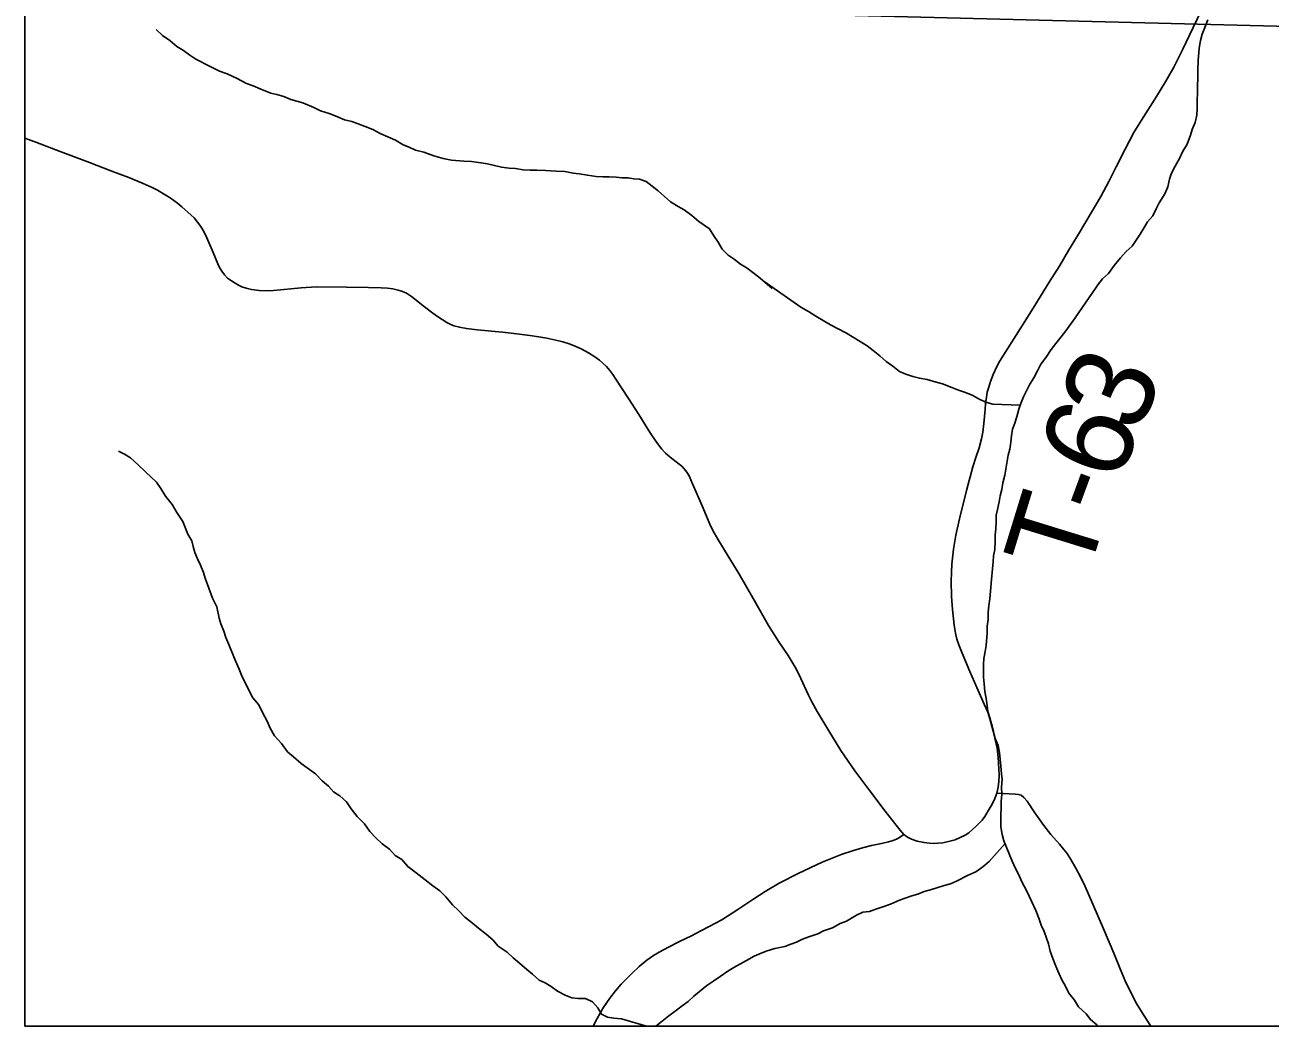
# Model space of a CAD drawing. Extents: x -3.3 to 34, y 0 to 56.8.
# Drawn here: x -3.304 to -2.5, y 28.077 to 28.724 of the extents above; entities that cross this region are included whole.
import ezdxf

# ---------------------------------------------------------------- set-up
doc = ezdxf.new("R2010")
doc.units = 0
for name, color, linetype in [('GM_X_Corporation', 7, 'Continuous'), ('GM_X_Township_Road', 7, 'Continuous'), ('GM_X_Township_Road_Text', 7, 'Continuous'), ('GT_Project_Soil_Layers', 7, 'Continuous'), ('SH_Data', 7, 'Continuous')]:
    doc.layers.add(name, color=color, linetype=linetype)

msp = doc.modelspace()

# ---------------------------------------------------------------- linework, layer by layer
at = {"layer": 'GM_X_Corporation'}
msp.add_lwpolyline([(-3.30393, 33.7379), (-3.30393, 28.07705), (1.56989, 28.07705), (1.59424, 28.73823), (1.64589, 29.81689), (1.65379, 30.0279), (1.68495, 30.79802), (1.68821, 30.98908), (1.68831, 30.9953), (1.68852, 31.00753), (1.69805, 31.56614), (1.74587, 32.36303)], dxfattribs=at)
msp.add_lwpolyline([(-3.30393, 29.75009), (-3.30393, 28.74342), (-2.4361, 28.72137), (-2.4143, 29.73246)], close=True, dxfattribs=at)
at = {"layer": 'GM_X_Township_Road'}
for points in [[(-2.67635, 28.22737), (-2.67545, 28.23132), (-2.67504, 28.23493), (-2.67479, 28.23913), (-2.67542, 28.25075), (-2.67624, 28.25659), (-2.67756, 28.26292), (-2.67871, 28.26744), (-2.68093, 28.2755), (-2.68225, 28.27969), (-2.68447, 28.28503), (-2.68931, 28.29563), (-2.69371, 28.30598), (-2.69877, 28.31791), (-2.70095, 28.32335), (-2.70214, 28.32687), (-2.70313, 28.33074), (-2.70395, 28.33592), (-2.70509, 28.34619), (-2.70559, 28.35458), (-2.70583, 28.36428), (-2.70573, 28.37007), (-2.70541, 28.37526), (-2.70428, 28.38514), (-2.70278, 28.39418), (-2.70055, 28.40469), (-2.69602, 28.42283), (-2.69177, 28.43816), (-2.68999, 28.44425), (-2.68785, 28.45049), (-2.68631, 28.45635), (-2.68547, 28.46063), (-2.68474, 28.46619), (-2.68397, 28.47517), (-2.68364, 28.47919), (-2.68314, 28.48331), (-2.68257, 28.48643), (-2.68178, 28.48911), (-2.68046, 28.49337), (-2.6787, 28.49794), (-2.67644, 28.50292), (-2.67461, 28.50632), (-2.67106, 28.51208), (-2.66388, 28.52332), (-2.65722, 28.53374), (-2.65009, 28.54525), (-2.64257, 28.55737), (-2.6358, 28.5683), (-2.63004, 28.57792), (-2.6237, 28.5885), (-2.61553, 28.60214), (-2.60921, 28.61269), (-2.60399, 28.62244), (-2.59926, 28.63186), (-2.59355, 28.64327), (-2.58787, 28.65403), (-2.58516, 28.65864), (-2.58303, 28.66201), (-2.57323, 28.67726), (-2.56724, 28.68717), (-2.56207, 28.69637), (-2.55648, 28.70755), (-2.5497, 28.72183), (-2.54447, 28.73271)], [(-3.30393, 28.65038), (-3.29681, 28.64792), (-3.28111, 28.64192), (-3.26225, 28.63473), (-3.24839, 28.62944), (-3.23682, 28.62502), (-3.22756, 28.62118), (-3.22185, 28.61857), (-3.21835, 28.61678), (-3.2134, 28.61391), (-3.21018, 28.61183), (-3.20548, 28.60843), (-3.20253, 28.60608), (-3.19475, 28.59901), (-3.19093, 28.59425), (-3.18966, 28.59234), (-3.18792, 28.58937), (-3.18643, 28.58619), (-3.18581, 28.58458), (-3.1824, 28.57654), (-3.17935, 28.56934), (-3.17828, 28.56703), (-3.1768, 28.56465), (-3.17499, 28.5621), (-3.17302, 28.56005), (-3.17063, 28.55832), (-3.16825, 28.55676), (-3.16603, 28.55552), (-3.1639, 28.55445), (-3.16116, 28.55353), (-3.15756, 28.55265), (-3.15271, 28.55199), (-3.14704, 28.55183), (-3.14351, 28.55207), (-3.12565, 28.55384), (-3.11556, 28.55445), (-3.09632, 28.55432), (-3.08202, 28.55412), (-3.07388, 28.55388), (-3.06977, 28.55355), (-3.06632, 28.55306), (-3.06303, 28.5524), (-3.06015, 28.5515), (-3.05744, 28.55026), (-3.05424, 28.54813), (-3.04585, 28.54163), (-3.04051, 28.53744), (-3.03755, 28.53522), (-3.03451, 28.53325), (-3.03146, 28.53136), (-3.02928, 28.53024), (-3.02696, 28.52934), (-3.02333, 28.52831), (-3.01889, 28.52749), (-3.0119, 28.52667), (-2.99562, 28.52511), (-2.98634, 28.52412), (-2.97787, 28.52306), (-2.9722, 28.52215), (-2.96685, 28.52125), (-2.9611, 28.52001), (-2.9565, 28.51886), (-2.95247, 28.51754), (-2.94869, 28.51615), (-2.94425, 28.51418), (-2.94005, 28.51187), (-2.93595, 28.50932), (-2.93282, 28.50711), (-2.92846, 28.503), (-2.92617, 28.50045), (-2.92436, 28.4979), (-2.92238, 28.49475), (-2.91415, 28.48225), (-2.90756, 28.47194), (-2.90019, 28.46009), (-2.89707, 28.45548), (-2.89476, 28.45236), (-2.89262, 28.44965), (-2.89024, 28.4471), (-2.88737, 28.44447), (-2.88145, 28.43987), (-2.87981, 28.43863), (-2.87824, 28.4369), (-2.87651, 28.43468), (-2.87511, 28.4323), (-2.87282, 28.42729), (-2.86665, 28.41299), (-2.86164, 28.40123), (-2.85966, 28.3972), (-2.85654, 28.39153), (-2.8498, 28.38043), (-2.84306, 28.36934), (-2.83313, 28.35203), (-2.82382, 28.3358), (-2.81719, 28.32519), (-2.81116, 28.31628), (-2.80658, 28.30892), (-2.80422, 28.30436), (-2.79798, 28.29077), (-2.79578, 28.28641), (-2.79248, 28.28018), (-2.78486, 28.26782), (-2.77705, 28.25499), (-2.76809, 28.24184), (-2.75838, 28.22892), (-2.7484, 28.21589), (-2.74146, 28.20682), (-2.73882, 28.20354), (-2.73634, 28.2007)], [(-2.73634, 28.2007), (-2.73412, 28.19907), (-2.73142, 28.19776), (-2.72792, 28.19656), (-2.72334, 28.19556), (-2.71986, 28.19516), (-2.71735, 28.19506), (-2.7145, 28.19513), (-2.7113, 28.19544), (-2.70669, 28.19638), (-2.70332, 28.19744), (-2.70005, 28.19879), (-2.69691, 28.20046), (-2.69456, 28.20196), (-2.68942, 28.20633), (-2.68588, 28.21008), (-2.68409, 28.21251), (-2.68122, 28.21712), (-2.67936, 28.22042), (-2.67776, 28.22397), (-2.67635, 28.22737)], [(-2.67635, 28.22737), (-2.66435, 28.22688), (-2.66246, 28.22663), (-2.66074, 28.22614), (-2.65885, 28.22474), (-2.65687, 28.22236), (-2.65178, 28.21471), (-2.64594, 28.20649), (-2.64142, 28.2008), (-2.63582, 28.19449), (-2.63303, 28.1912), (-2.63098, 28.18849), (-2.62851, 28.18455), (-2.62539, 28.17895), (-2.62218, 28.17304), (-2.6193, 28.16712), (-2.61437, 28.15586), (-2.60759, 28.13989), (-2.60089, 28.12412), (-2.5967, 28.11393), (-2.59341, 28.10629), (-2.59028, 28.09971), (-2.5861, 28.09158), (-2.58127, 28.08363), (-2.57697, 28.07705)], [(-2.93699, 28.07705), (-2.93442, 28.08186), (-2.9305, 28.08877), (-2.92615, 28.09519), (-2.92256, 28.09992), (-2.9189, 28.10419), (-2.91233, 28.11085), (-2.90731, 28.11553), (-2.9023, 28.11964), (-2.8981, 28.1226), (-2.89449, 28.12482), (-2.88832, 28.12811), (-2.88118, 28.13169), (-2.87353, 28.1354), (-2.86745, 28.13847), (-2.86202, 28.14134), (-2.85388, 28.14578), (-2.8436, 28.15228), (-2.83382, 28.15885), (-2.82591, 28.16398), (-2.81687, 28.16925), (-2.80462, 28.17567), (-2.78905, 28.18297), (-2.78169, 28.18599), (-2.77624, 28.18801), (-2.76951, 28.19026), (-2.76307, 28.19215), (-2.75722, 28.19362), (-2.7508, 28.19502), (-2.74638, 28.19608), (-2.74339, 28.19687), (-2.74082, 28.19791), (-2.73852, 28.19917), (-2.73634, 28.2007)]]:
    msp.add_lwpolyline(points, dxfattribs=at)
at = {"layer": 'GT_Project_Soil_Layers'}
for points in [[(-3.21923, 28.72055), (-3.21501, 28.71682), (-3.21041, 28.71346), (-3.20581, 28.70973), (-3.20161, 28.70713), (-3.19739, 28.70416), (-3.19357, 28.70155), (-3.1844, 28.69674), (-3.1783, 28.69379), (-3.17334, 28.69196), (-3.16686, 28.68902), (-3.16075, 28.68569), (-3.15656, 28.68423), (-3.15159, 28.68202), (-3.14511, 28.67945), (-3.14131, 28.67874), (-3.13674, 28.67729), (-3.13217, 28.67545), (-3.12456, 28.67328), (-3.11731, 28.67034), (-3.11311, 28.66812), (-3.1074, 28.66631), (-3.10245, 28.66448), (-3.09749, 28.66227), (-3.09292, 28.66119), (-3.08873, 28.65973), (-3.08416, 28.65789), (-3.0792, 28.65607), (-3.07462, 28.65347), (-3.06966, 28.65127), (-3.0647, 28.64906), (-3.05973, 28.64609), (-3.05592, 28.64462), (-3.05172, 28.64278), (-3.04639, 28.64134), (-3.03992, 28.63915), (-3.03383, 28.63734), (-3.02851, 28.63627), (-3.02053, 28.63562), (-3.0156, 28.63531), (-3.00952, 28.63463), (-3.00534, 28.63393), (-3.00078, 28.63285), (-2.99621, 28.63178), (-2.99128, 28.63109), (-2.9871, 28.63077), (-2.98216, 28.63007), (-2.97761, 28.62976), (-2.97344, 28.62982), (-2.96774, 28.62951), (-2.96092, 28.62923), (-2.95522, 28.62892), (-2.9499, 28.62786), (-2.94611, 28.62753), (-2.94078, 28.62647), (-2.93509, 28.62578), (-2.93053, 28.62547), (-2.92674, 28.62552), (-2.92219, 28.62521), (-2.91839, 28.62488), (-2.9146, 28.62493), (-2.9108, 28.62422), (-2.907, 28.62389), (-2.90281, 28.62243), (-2.89515, 28.61647), (-2.88709, 28.60937), (-2.88212, 28.6064), (-2.8783, 28.60418), (-2.87332, 28.60045), (-2.86872, 28.59672), (-2.86183, 28.59188), (-2.85911, 28.58736), (-2.8564, 28.58323), (-2.85369, 28.57871), (-2.84984, 28.57497), (-2.84602, 28.57237), (-2.8418, 28.56901), (-2.83759, 28.56641), (-2.833, 28.56306), (-2.82917, 28.56008), (-2.82149, 28.55335)], [(-2.5402, 28.72681), (-2.54167, 28.72299), (-2.54387, 28.71765), (-2.54495, 28.71346), (-2.54564, 28.70852), (-2.5463, 28.70054), (-2.54659, 28.69447), (-2.54652, 28.68916), (-2.54683, 28.68422), (-2.54678, 28.68005), (-2.54709, 28.67473), (-2.54702, 28.6698), (-2.54734, 28.66524), (-2.54841, 28.66067), (-2.55025, 28.6561), (-2.55133, 28.65229), (-2.55353, 28.64657), (-2.5565, 28.64159), (-2.55834, 28.63739), (-2.5613, 28.63242), (-2.56352, 28.62784), (-2.56498, 28.62402), (-2.56605, 28.61907), (-2.56789, 28.6145), (-2.5716, 28.60875), (-2.57345, 28.60493), (-2.57566, 28.60035), (-2.57902, 28.59651), (-2.58124, 28.59269), (-2.58384, 28.58848), (-2.58905, 28.58082), (-2.59279, 28.57735), (-2.59653, 28.57313), (-2.60063, 28.56814), (-2.60436, 28.56315), (-2.6081, 28.55969), (-2.61108, 28.55585)], [(-2.82657, 28.5578), (-2.80292, 28.54141), (-2.79794, 28.53842), (-2.79334, 28.53542), (-2.78377, 28.52981), (-2.77918, 28.52757), (-2.77344, 28.52459), (-2.76846, 28.52159), (-2.76004, 28.51635), (-2.7562, 28.51335), (-2.75198, 28.50997), (-2.74776, 28.50621), (-2.74354, 28.5032), (-2.73932, 28.49982), (-2.73511, 28.49796), (-2.73053, 28.49649), (-2.72633, 28.49539), (-2.72138, 28.49467), (-2.71564, 28.49283), (-2.71145, 28.49173), (-2.70533, 28.4895), (-2.70113, 28.48764), (-2.69654, 28.48617), (-2.69195, 28.48431), (-2.68736, 28.48169), (-2.68277, 28.47984), (-2.67895, 28.47873), (-2.66126, 28.47804)], [(-2.61002, 28.55721), (-2.62576, 28.53437), (-2.63178, 28.52595), (-2.63479, 28.52212), (-2.63818, 28.5179), (-2.64119, 28.51407), (-2.64457, 28.5091), (-2.64796, 28.5045), (-2.65021, 28.5003), (-2.65245, 28.49571), (-2.65508, 28.49151), (-2.65732, 28.4873), (-2.65919, 28.48349), (-2.66068, 28.47967), (-2.66217, 28.47547), (-2.66327, 28.47128), (-2.66475, 28.46632), (-2.66624, 28.46251), (-2.66696, 28.45832), (-2.66731, 28.45413), (-2.66803, 28.44957), (-2.66913, 28.44575), (-2.67057, 28.43661), (-2.6713, 28.43281), (-2.6724, 28.42785), (-2.67312, 28.42367), (-2.67423, 28.41947), (-2.67495, 28.41567), (-2.67605, 28.41071), (-2.67678, 28.4069), (-2.67674, 28.40272), (-2.67708, 28.39816), (-2.67743, 28.39435), (-2.67739, 28.39017), (-2.67772, 28.38484), (-2.67845, 28.38066), (-2.67879, 28.37685), (-2.67913, 28.37229), (-2.67983, 28.36544), (-2.68052, 28.35783), (-2.68086, 28.35288), (-2.68158, 28.34869), (-2.68192, 28.34413), (-2.68188, 28.33957), (-2.6826, 28.33538), (-2.68256, 28.33082), (-2.68325, 28.32282), (-2.68398, 28.31902), (-2.6847, 28.31445), (-2.68505, 28.31064), (-2.68497, 28.30228), (-2.68455, 28.2981), (-2.68412, 28.29316), (-2.68332, 28.28861), (-2.68252, 28.28406), (-2.6821, 28.28026), (-2.68092, 28.27609), (-2.67974, 28.2723), (-2.67856, 28.26737), (-2.67738, 28.26282), (-2.67543, 28.25827), (-2.67463, 28.25372), (-2.67378, 28.24498), (-2.67336, 28.24004), (-2.67294, 28.23625), (-2.67328, 28.2313), (-2.67324, 28.22674), (-2.67358, 28.22218), (-2.67354, 28.21761), (-2.67388, 28.21381), (-2.67381, 28.20583), (-2.673, 28.20089), (-2.67182, 28.19672), (-2.66637, 28.18347), (-2.66442, 28.17892), (-2.66249, 28.17514), (-2.66016, 28.17022), (-2.65706, 28.16417), (-2.65395, 28.15774), (-2.65123, 28.15168), (-2.64928, 28.14676), (-2.64772, 28.14221), (-2.64577, 28.13805), (-2.64421, 28.13388), (-2.64303, 28.13009), (-2.64185, 28.12554), (-2.64028, 28.12061), (-2.63833, 28.11569), (-2.63639, 28.11114), (-2.63445, 28.10698), (-2.63212, 28.10282), (-2.6298, 28.09828), (-2.62633, 28.09375), (-2.62362, 28.0896), (-2.61863, 28.08508), (-2.61593, 28.08131), (-2.61171, 28.07793), (-2.6109, 28.07705)], [(-3.24348, 28.44823), (-3.23965, 28.44637), (-3.23582, 28.44412), (-3.23083, 28.43961), (-3.22583, 28.43471), (-3.21892, 28.42832), (-3.21622, 28.42416), (-3.21313, 28.41925), (-3.20889, 28.41397), (-3.20579, 28.40867), (-3.20193, 28.40301), (-3.19881, 28.39468), (-3.19611, 28.39052), (-3.19531, 28.38673), (-3.19413, 28.38293), (-3.19257, 28.37877), (-3.19063, 28.37461), (-3.18869, 28.37006), (-3.18751, 28.36627), (-3.18282, 28.35339), (-3.1801, 28.34771), (-3.17851, 28.34051), (-3.17734, 28.33672), (-3.17539, 28.33217), (-3.17421, 28.328), (-3.17227, 28.32346), (-3.16954, 28.31664), (-3.16798, 28.31285), (-3.16565, 28.30756), (-3.1637, 28.30263), (-3.15672, 28.28901), (-3.15287, 28.28449), (-3.15054, 28.27957), (-3.14744, 28.2739), (-3.1455, 28.26935), (-3.14278, 28.26444), (-3.13817, 28.25954), (-3.13431, 28.25425), (-3.13047, 28.25087), (-3.12549, 28.24674), (-3.11628, 28.23998), (-3.11205, 28.23546), (-3.10783, 28.23208), (-3.10475, 28.22831), (-3.10054, 28.22568), (-3.09632, 28.22192), (-3.09323, 28.21739), (-3.08938, 28.21249), (-3.08476, 28.20759), (-3.08129, 28.20268), (-3.07744, 28.19853), (-3.07322, 28.19477), (-3.06862, 28.1914), (-3.06477, 28.18725), (-3.06056, 28.18463), (-3.05671, 28.18011), (-3.05134, 28.17597), (-3.04559, 28.17147), (-3.0406, 28.16771), (-3.036, 28.16434), (-3.03216, 28.16057), (-3.02792, 28.15529), (-3.0237, 28.15153), (-3.01985, 28.14739), (-3.01487, 28.14363), (-3.01102, 28.14025), (-3.00604, 28.13649), (-3.00182, 28.13273), (-2.99835, 28.12858), (-2.9926, 28.12484), (-2.98876, 28.12107), (-2.98454, 28.11769), (-2.97994, 28.11355), (-2.9761, 28.11055), (-2.97188, 28.10679), (-2.96805, 28.10492), (-2.96422, 28.10268), (-2.96, 28.09968), (-2.95503, 28.09706), (-2.95082, 28.0952), (-2.94663, 28.09486), (-2.94206, 28.09491), (-2.93747, 28.09267), (-2.93401, 28.0889), (-2.93169, 28.08474), (-2.92786, 28.08288), (-2.92367, 28.08216), (-2.91871, 28.08183), (-2.90263, 28.07705)], [(-2.6711, 28.19496), (-2.68122, 28.18332), (-2.68538, 28.17986), (-2.68992, 28.17678), (-2.69485, 28.17445), (-2.70243, 28.17058), (-2.70623, 28.16902), (-2.71041, 28.16784), (-2.71914, 28.1651), (-2.72332, 28.16391), (-2.72749, 28.16235), (-2.73129, 28.16118), (-2.73547, 28.15962), (-2.73927, 28.15844), (-2.74495, 28.15572), (-2.74989, 28.15415), (-2.75445, 28.15259), (-2.75862, 28.15103), (-2.76281, 28.15061), (-2.76698, 28.14867), (-2.77342, 28.14481), (-2.77759, 28.14325), (-2.78252, 28.14054), (-2.78821, 28.13858), (-2.79201, 28.13664), (-2.7977, 28.13469), (-2.80188, 28.13313), (-2.80567, 28.13119), (-2.80946, 28.13001), (-2.81326, 28.12846), (-2.81972, 28.12725), (-2.82466, 28.12569), (-2.82845, 28.12413), (-2.83301, 28.12218), (-2.83793, 28.11948), (-2.84627, 28.11483), (-2.85006, 28.11252), (-2.85498, 28.10905), (-2.85914, 28.10635), (-2.86368, 28.10326), (-2.872, 28.09634), (-2.87578, 28.09288), (-2.87956, 28.09018), (-2.8841, 28.08672), (-2.88826, 28.08364), (-2.89242, 28.08018), (-2.89651, 28.07705)]]:
    msp.add_lwpolyline(points, dxfattribs=at)
at = {"layer": 'SH_Data'}
for p, q in [((-3.30393, 34.87705), (-3.30393, 28.07705)), ((-3.30393, 28.07705), (3.49607, 28.07705)), ((-3.30393, 28.07705), (-3.30393, 28.07705))]:
    msp.add_line(p, q, dxfattribs=at)

# ---------------------------------------------------------------- texts
at = {"layer": 'GM_X_Township_Road_Text'}
for s, rotation, p in [('3', 66.8301, (-2.58541, 28.45837)), ('6', 68.42278, (-2.59812, 28.42621)), ('-', 69.82949, (-2.60603, 28.40465)), ('T', 72.86481, (-2.6183, 28.36479))]:
    msp.add_text(s, height=0.05682, rotation=rotation, dxfattribs=at).set_placement(p)

doc.saveas('drawing.dxf')
